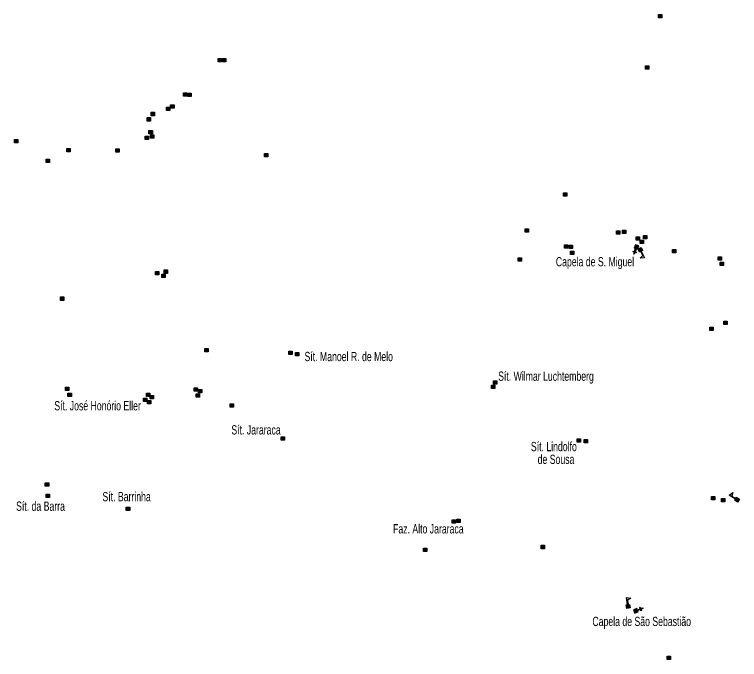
# Model space of a CAD drawing. Extents: x 647.8 to 672.9, y 6929.3 to 6957.3.
# Drawn here: x 654.09 to 660.33, y 6943.48 to 6949.04 of the extents above; entities that cross this region are included whole.
import ezdxf
from ezdxf.enums import TextEntityAlignment as Align

# ---------------------------------------------------------------- set-up
doc = ezdxf.new("R2010")
doc.units = 0
doc.header["$LTSCALE"] = 0.032
for name, color, linetype, lineweight in [('2', 7, 'Continuous', 25), ('4', 7, 'Continuous', 25), ('6', 7, 'Continuous', 25)]:
    doc.layers.add(name, color=color, linetype=linetype, lineweight=lineweight)
doc.layers.add('61', color=7, linetype='Continuous')

msp = doc.modelspace()

# ---------------------------------------------------------------- hatches: boundary and pattern name
at = {"layer": '2'}
for points in [[(659.6357, 6949.0383), (659.6647, 6949.0383), (659.6647, 6949.0093), (659.6357, 6949.0093)], [(655.8425, 6948.6588), (655.8715, 6948.6588), (655.8715, 6948.6298), (655.8425, 6948.6298)], [(655.882, 6948.6588), (655.911, 6948.6588), (655.911, 6948.6298), (655.882, 6948.6298)], [(659.5238, 6948.5951), (659.5528, 6948.5951), (659.5528, 6948.5661), (659.5238, 6948.5661)], [(655.5442, 6948.3626), (655.5732, 6948.3626), (655.5732, 6948.3336), (655.5442, 6948.3336)], [(655.5815, 6948.3604), (655.6105, 6948.3604), (655.6105, 6948.3314), (655.5815, 6948.3314)], [(655.3994, 6948.2397), (655.4284, 6948.2397), (655.4284, 6948.2107), (655.3994, 6948.2107)], [(655.4345, 6948.2617), (655.4635, 6948.2617), (655.4635, 6948.2327), (655.4345, 6948.2327)], [(655.2326, 6948.1498), (655.2616, 6948.1498), (655.2616, 6948.1208), (655.2326, 6948.1208)], [(655.2677, 6948.1959), (655.2967, 6948.1959), (655.2967, 6948.1669), (655.2677, 6948.1669)], [(655.248, 6948.0401), (655.277, 6948.0401), (655.277, 6948.0111), (655.248, 6948.0111)], [(654.0896, 6947.9611), (654.1186, 6947.9611), (654.1186, 6947.9321), (654.0896, 6947.9321)], [(655.2151, 6947.9896), (655.2441, 6947.9896), (655.2441, 6947.9606), (655.2151, 6947.9606)], [(655.2612, 6948.0028), (655.2902, 6948.0028), (655.2902, 6947.9738), (655.2612, 6947.9738)], [(654.5394, 6947.8843), (654.5684, 6947.8843), (654.5684, 6947.8553), (654.5394, 6947.8553)], [(654.9628, 6947.8821), (654.9918, 6947.8821), (654.9918, 6947.8531), (654.9628, 6947.8531)], [(656.244, 6947.8405), (656.273, 6947.8405), (656.273, 6947.8115), (656.244, 6947.8115)], [(654.3617, 6947.7922), (654.3907, 6947.7922), (654.3907, 6947.7632), (654.3617, 6947.7632)], [(658.8174, 6947.5026), (658.8464, 6947.5026), (658.8464, 6947.4736), (658.8174, 6947.4736)], [(658.4883, 6947.1933), (658.5173, 6947.1933), (658.5173, 6947.1643), (658.4883, 6947.1643)], [(659.2737, 6947.1757), (659.3027, 6947.1757), (659.3027, 6947.1467), (659.2737, 6947.1467)], [(659.3264, 6947.1801), (659.3554, 6947.1801), (659.3554, 6947.1511), (659.3264, 6947.1511)], [(659.4438, 6947.1236), (659.4728, 6947.1236), (659.4728, 6947.0946), (659.4438, 6947.0946)], [(659.4777, 6947.0945), (659.5067, 6947.0945), (659.5067, 6947.0655), (659.4777, 6947.0655)], [(659.5084, 6947.134), (659.5374, 6947.134), (659.5374, 6947.105), (659.5084, 6947.105)], [(658.8262, 6947.0551), (658.8552, 6947.0551), (658.8552, 6947.0261), (658.8262, 6947.0261)], [(658.8678, 6947.0529), (658.8968, 6947.0529), (658.8968, 6947.0239), (658.8678, 6947.0239)], [(658.8788, 6947.0002), (658.9078, 6947.0002), (658.9078, 6946.9712), (658.8788, 6946.9712)], [(659.7585, 6947.0134), (659.7875, 6947.0134), (659.7875, 6946.9844), (659.7585, 6946.9844)], [(660.1512, 6946.9519), (660.1802, 6946.9519), (660.1802, 6946.9229), (660.1512, 6946.9229)], [(658.4291, 6946.9432), (658.4581, 6946.9432), (658.4581, 6946.9142), (658.4291, 6946.9142)], [(660.1688, 6946.9059), (660.1978, 6946.9059), (660.1978, 6946.8769), (660.1688, 6946.8769)], [(655.3796, 6946.8379), (655.4086, 6946.8379), (655.4086, 6946.8089), (655.3796, 6946.8089)], [(655.305, 6946.8247), (655.334, 6946.8247), (655.334, 6946.7957), (655.305, 6946.7957)], [(655.3577, 6946.8028), (655.3867, 6946.8028), (655.3867, 6946.7738), (655.3577, 6946.7738)], [(654.4867, 6946.6053), (654.5157, 6946.6053), (654.5157, 6946.5763), (654.4867, 6946.5763)], [(660.1995, 6946.3969), (660.2285, 6946.3969), (660.2285, 6946.3679), (660.1995, 6946.3679)], [(660.0788, 6946.3464), (660.1078, 6946.3464), (660.1078, 6946.3174), (660.0788, 6946.3174)], [(655.7284, 6946.1622), (655.7574, 6946.1622), (655.7574, 6946.1332), (655.7284, 6946.1332)], [(656.4524, 6946.138), (656.4814, 6946.138), (656.4814, 6946.109), (656.4524, 6946.109)], [(656.5095, 6946.1271), (656.5385, 6946.1271), (656.5385, 6946.0981), (656.5095, 6946.0981)], [(654.5284, 6945.8287), (654.5574, 6945.8287), (654.5574, 6945.7997), (654.5284, 6945.7997)], [(658.1987, 6945.8462), (658.2277, 6945.8462), (658.2277, 6945.8172), (658.1987, 6945.8172)], [(658.2163, 6945.8835), (658.2453, 6945.8835), (658.2453, 6945.8545), (658.2163, 6945.8545)], [(654.5503, 6945.776), (654.5793, 6945.776), (654.5793, 6945.747), (654.5503, 6945.747)], [(655.2261, 6945.776), (655.2551, 6945.776), (655.2551, 6945.747), (655.2261, 6945.747)], [(655.6363, 6945.8221), (655.6653, 6945.8221), (655.6653, 6945.7931), (655.6363, 6945.7931)], [(655.6539, 6945.7717), (655.6829, 6945.7717), (655.6829, 6945.7427), (655.6539, 6945.7427)], [(655.6736, 6945.809), (655.7026, 6945.809), (655.7026, 6945.78), (655.6736, 6945.78)], [(655.1997, 6945.7344), (655.2287, 6945.7344), (655.2287, 6945.7054), (655.1997, 6945.7054)], [(655.2348, 6945.7146), (655.2638, 6945.7146), (655.2638, 6945.6856), (655.2348, 6945.6856)], [(655.2568, 6945.7563), (655.2858, 6945.7563), (655.2858, 6945.7273), (655.2568, 6945.7273)], [(655.9478, 6945.6839), (655.9768, 6945.6839), (655.9768, 6945.6549), (655.9478, 6945.6549)], [(656.3866, 6945.4009), (656.4156, 6945.4009), (656.4156, 6945.3719), (656.3866, 6945.3719)], [(658.9358, 6945.3833), (658.9648, 6945.3833), (658.9648, 6945.3543), (658.9358, 6945.3543)], [(658.9951, 6945.379), (659.0241, 6945.379), (659.0241, 6945.35), (658.9951, 6945.35)], [(654.3551, 6945.0038), (654.3841, 6945.0038), (654.3841, 6944.9748), (654.3551, 6944.9748)], [(654.3617, 6944.9073), (654.3907, 6944.9073), (654.3907, 6944.8783), (654.3617, 6944.8783)], [(660.0942, 6944.8875), (660.1232, 6944.8875), (660.1232, 6944.8585), (660.0942, 6944.8585)], [(660.1798, 6944.87), (660.2088, 6944.87), (660.2088, 6944.841), (660.1798, 6944.841)], [(655.0527, 6944.7954), (655.0817, 6944.7954), (655.0817, 6944.7664), (655.0527, 6944.7664)], [(657.8587, 6944.6857), (657.8877, 6944.6857), (657.8877, 6944.6567), (657.8587, 6944.6567)], [(657.9004, 6944.6923), (657.9294, 6944.6923), (657.9294, 6944.6633), (657.9004, 6944.6633)], [(658.6265, 6944.4663), (658.6555, 6944.4663), (658.6555, 6944.4373), (658.6265, 6944.4373)], [(657.613, 6944.4422), (657.642, 6944.4422), (657.642, 6944.4132), (657.613, 6944.4132)], [(659.7103, 6943.512), (659.7393, 6943.512), (659.7393, 6943.483), (659.7103, 6943.483)]]:
    msp.add_hatch(color=256, dxfattribs=at).paths.add_polyline_path(points)
at = {"layer": '4'}
for points in [[(659.4873, 6947.0324), (659.5002, 6947.0054), (659.4731, 6946.9924), (659.4602, 6947.0195)], [(660.3187, 6944.8385), (660.2932, 6944.8543), (660.309, 6944.8798), (660.3345, 6944.864)], [(659.3634, 6943.9234), (659.3585, 6943.953), (659.3881, 6943.9579), (659.393, 6943.9283)]]:
    msp.add_hatch(color=256, dxfattribs=at).paths.add_polyline_path(points)
at = {"layer": '6'}
for points in [[(659.4397, 6947.0218), (659.4444, 6947.0202), (659.4355, 6946.9941), (659.4474, 6946.9901), (659.4457, 6946.9854), (659.4339, 6946.9894), (659.4282, 6946.9729), (659.4235, 6946.9744), (659.4292, 6946.9911), (659.4174, 6946.9951), (659.4189, 6946.9998), (659.4308, 6946.9958)], [(659.4562, 6947.0161), (659.466, 6947.0445), (659.4375, 6947.0542), (659.4278, 6947.0258)], [(659.4495, 6943.9209), (659.4215, 6943.9101), (659.4323, 6943.8821), (659.4603, 6943.8929)], [(659.4558, 6943.9045), (659.454, 6943.9092), (659.4796, 6943.9191), (659.4752, 6943.9307), (659.4798, 6943.9325), (659.4843, 6943.9209), (659.5006, 6943.9272), (659.5024, 6943.9225), (659.4861, 6943.9162), (659.4906, 6943.9045), (659.4859, 6943.9027), (659.4814, 6943.9144)]]:
    msp.add_hatch(color=256, dxfattribs=at).paths.add_polyline_path(points)

# ---------------------------------------------------------------- linework, layer by layer
at = {"layer": '2'}
for points in [[(659.6357, 6949.0383), (659.6647, 6949.0383), (659.6647, 6949.0093), (659.6357, 6949.0093)], [(655.8425, 6948.6588), (655.8715, 6948.6588), (655.8715, 6948.6298), (655.8425, 6948.6298)], [(655.882, 6948.6588), (655.911, 6948.6588), (655.911, 6948.6298), (655.882, 6948.6298)], [(659.5238, 6948.5951), (659.5528, 6948.5951), (659.5528, 6948.5661), (659.5238, 6948.5661)], [(655.5442, 6948.3626), (655.5732, 6948.3626), (655.5732, 6948.3336), (655.5442, 6948.3336)], [(655.5815, 6948.3604), (655.6105, 6948.3604), (655.6105, 6948.3314), (655.5815, 6948.3314)], [(655.3994, 6948.2397), (655.4284, 6948.2397), (655.4284, 6948.2107), (655.3994, 6948.2107)], [(655.4345, 6948.2617), (655.4635, 6948.2617), (655.4635, 6948.2327), (655.4345, 6948.2327)], [(655.2326, 6948.1498), (655.2616, 6948.1498), (655.2616, 6948.1208), (655.2326, 6948.1208)], [(655.2677, 6948.1959), (655.2967, 6948.1959), (655.2967, 6948.1669), (655.2677, 6948.1669)], [(655.248, 6948.0401), (655.277, 6948.0401), (655.277, 6948.0111), (655.248, 6948.0111)], [(654.0896, 6947.9611), (654.1186, 6947.9611), (654.1186, 6947.9321), (654.0896, 6947.9321)], [(655.2151, 6947.9896), (655.2441, 6947.9896), (655.2441, 6947.9606), (655.2151, 6947.9606)], [(655.2612, 6948.0028), (655.2902, 6948.0028), (655.2902, 6947.9738), (655.2612, 6947.9738)], [(654.5394, 6947.8843), (654.5684, 6947.8843), (654.5684, 6947.8553), (654.5394, 6947.8553)], [(654.9628, 6947.8821), (654.9918, 6947.8821), (654.9918, 6947.8531), (654.9628, 6947.8531)], [(656.244, 6947.8405), (656.273, 6947.8405), (656.273, 6947.8115), (656.244, 6947.8115)], [(654.3617, 6947.7922), (654.3907, 6947.7922), (654.3907, 6947.7632), (654.3617, 6947.7632)], [(658.8174, 6947.5026), (658.8464, 6947.5026), (658.8464, 6947.4736), (658.8174, 6947.4736)], [(658.4883, 6947.1933), (658.5173, 6947.1933), (658.5173, 6947.1643), (658.4883, 6947.1643)], [(659.2737, 6947.1757), (659.3027, 6947.1757), (659.3027, 6947.1467), (659.2737, 6947.1467)], [(659.3264, 6947.1801), (659.3554, 6947.1801), (659.3554, 6947.1511), (659.3264, 6947.1511)], [(659.4438, 6947.1236), (659.4728, 6947.1236), (659.4728, 6947.0946), (659.4438, 6947.0946)], [(659.4777, 6947.0945), (659.5067, 6947.0945), (659.5067, 6947.0655), (659.4777, 6947.0655)], [(659.5084, 6947.134), (659.5374, 6947.134), (659.5374, 6947.105), (659.5084, 6947.105)], [(658.8262, 6947.0551), (658.8552, 6947.0551), (658.8552, 6947.0261), (658.8262, 6947.0261)], [(658.8678, 6947.0529), (658.8968, 6947.0529), (658.8968, 6947.0239), (658.8678, 6947.0239)], [(658.8788, 6947.0002), (658.9078, 6947.0002), (658.9078, 6946.9712), (658.8788, 6946.9712)], [(659.7585, 6947.0134), (659.7875, 6947.0134), (659.7875, 6946.9844), (659.7585, 6946.9844)], [(660.1512, 6946.9519), (660.1802, 6946.9519), (660.1802, 6946.9229), (660.1512, 6946.9229)], [(658.4291, 6946.9432), (658.4581, 6946.9432), (658.4581, 6946.9142), (658.4291, 6946.9142)], [(660.1688, 6946.9059), (660.1978, 6946.9059), (660.1978, 6946.8769), (660.1688, 6946.8769)], [(655.3796, 6946.8379), (655.4086, 6946.8379), (655.4086, 6946.8089), (655.3796, 6946.8089)], [(655.305, 6946.8247), (655.334, 6946.8247), (655.334, 6946.7957), (655.305, 6946.7957)], [(655.3577, 6946.8028), (655.3867, 6946.8028), (655.3867, 6946.7738), (655.3577, 6946.7738)], [(654.4867, 6946.6053), (654.5157, 6946.6053), (654.5157, 6946.5763), (654.4867, 6946.5763)], [(660.1995, 6946.3969), (660.2285, 6946.3969), (660.2285, 6946.3679), (660.1995, 6946.3679)], [(660.0788, 6946.3464), (660.1078, 6946.3464), (660.1078, 6946.3174), (660.0788, 6946.3174)], [(655.7284, 6946.1622), (655.7574, 6946.1622), (655.7574, 6946.1332), (655.7284, 6946.1332)], [(656.4524, 6946.138), (656.4814, 6946.138), (656.4814, 6946.109), (656.4524, 6946.109)], [(656.5095, 6946.1271), (656.5385, 6946.1271), (656.5385, 6946.0981), (656.5095, 6946.0981)], [(654.5284, 6945.8287), (654.5574, 6945.8287), (654.5574, 6945.7997), (654.5284, 6945.7997)], [(658.1987, 6945.8462), (658.2277, 6945.8462), (658.2277, 6945.8172), (658.1987, 6945.8172)], [(658.2163, 6945.8835), (658.2453, 6945.8835), (658.2453, 6945.8545), (658.2163, 6945.8545)], [(654.5503, 6945.776), (654.5793, 6945.776), (654.5793, 6945.747), (654.5503, 6945.747)], [(655.2261, 6945.776), (655.2551, 6945.776), (655.2551, 6945.747), (655.2261, 6945.747)], [(655.6363, 6945.8221), (655.6653, 6945.8221), (655.6653, 6945.7931), (655.6363, 6945.7931)], [(655.6539, 6945.7717), (655.6829, 6945.7717), (655.6829, 6945.7427), (655.6539, 6945.7427)], [(655.6736, 6945.809), (655.7026, 6945.809), (655.7026, 6945.78), (655.6736, 6945.78)], [(655.1997, 6945.7344), (655.2287, 6945.7344), (655.2287, 6945.7054), (655.1997, 6945.7054)], [(655.2348, 6945.7146), (655.2638, 6945.7146), (655.2638, 6945.6856), (655.2348, 6945.6856)], [(655.2568, 6945.7563), (655.2858, 6945.7563), (655.2858, 6945.7273), (655.2568, 6945.7273)], [(655.9478, 6945.6839), (655.9768, 6945.6839), (655.9768, 6945.6549), (655.9478, 6945.6549)], [(656.3866, 6945.4009), (656.4156, 6945.4009), (656.4156, 6945.3719), (656.3866, 6945.3719)], [(658.9358, 6945.3833), (658.9648, 6945.3833), (658.9648, 6945.3543), (658.9358, 6945.3543)], [(658.9951, 6945.379), (659.0241, 6945.379), (659.0241, 6945.35), (658.9951, 6945.35)], [(654.3551, 6945.0038), (654.3841, 6945.0038), (654.3841, 6944.9748), (654.3551, 6944.9748)], [(654.3617, 6944.9073), (654.3907, 6944.9073), (654.3907, 6944.8783), (654.3617, 6944.8783)], [(660.0942, 6944.8875), (660.1232, 6944.8875), (660.1232, 6944.8585), (660.0942, 6944.8585)], [(660.1798, 6944.87), (660.2088, 6944.87), (660.2088, 6944.841), (660.1798, 6944.841)], [(655.0527, 6944.7954), (655.0817, 6944.7954), (655.0817, 6944.7664), (655.0527, 6944.7664)], [(657.8587, 6944.6857), (657.8877, 6944.6857), (657.8877, 6944.6567), (657.8587, 6944.6567)], [(657.9004, 6944.6923), (657.9294, 6944.6923), (657.9294, 6944.6633), (657.9004, 6944.6633)], [(658.6265, 6944.4663), (658.6555, 6944.4663), (658.6555, 6944.4373), (658.6265, 6944.4373)], [(657.613, 6944.4422), (657.642, 6944.4422), (657.642, 6944.4132), (657.613, 6944.4132)], [(659.7103, 6943.512), (659.7393, 6943.512), (659.7393, 6943.483), (659.7103, 6943.483)]]:
    msp.add_lwpolyline(points, close=True, dxfattribs=at)
at = {"layer": '4'}
for p, q in [((659.4889, 6947), (659.4844, 6946.9978)), ((660.2997, 6944.8649), (660.3024, 6944.8692)), ((659.3708, 6943.955), (659.3758, 6943.9558))]:
    msp.add_line(p, q, dxfattribs=at)
for points in [[(659.4873, 6947.0324), (659.5002, 6947.0054), (659.4731, 6946.9924), (659.4602, 6947.0195)], [(659.4889, 6947), (659.5158, 6946.9436), (659.4789, 6946.9398), (659.5014, 6946.9622), (659.4844, 6946.9978)], [(660.2997, 6944.8649), (660.2466, 6944.8978), (660.2757, 6944.921), (660.2688, 6944.89), (660.3024, 6944.8692)], [(660.3187, 6944.8385), (660.2932, 6944.8543), (660.309, 6944.8798), (660.3345, 6944.864)], [(659.3708, 6943.955), (659.3606, 6944.0167), (659.3972, 6944.0101), (659.3693, 6943.9948), (659.3758, 6943.9558)], [(659.3634, 6943.9234), (659.3585, 6943.953), (659.3881, 6943.9579), (659.393, 6943.9283)]]:
    msp.add_lwpolyline(points, close=True, dxfattribs=at)
at = {"layer": '6'}
for points in [[(659.4397, 6947.0218), (659.4444, 6947.0202), (659.4355, 6946.9941), (659.4474, 6946.9901), (659.4457, 6946.9854), (659.4339, 6946.9894), (659.4282, 6946.9729), (659.4235, 6946.9744), (659.4292, 6946.9911), (659.4174, 6946.9951), (659.4189, 6946.9998), (659.4308, 6946.9958)], [(659.4562, 6947.0161), (659.466, 6947.0445), (659.4375, 6947.0542), (659.4278, 6947.0258)], [(659.4495, 6943.9209), (659.4215, 6943.9101), (659.4323, 6943.8821), (659.4603, 6943.8929)], [(659.4558, 6943.9045), (659.454, 6943.9092), (659.4796, 6943.9191), (659.4752, 6943.9307), (659.4798, 6943.9325), (659.4843, 6943.9209), (659.5006, 6943.9272), (659.5024, 6943.9225), (659.4861, 6943.9162), (659.4906, 6943.9045), (659.4859, 6943.9027), (659.4814, 6943.9144)]]:
    msp.add_lwpolyline(points, close=True, dxfattribs=at)

# ---------------------------------------------------------------- texts
at = {"layer": '61', "width": 0.7}
for s, p in [('Capela de S. Miguel', (659.4269, 6946.8691)), ('Sít. José Honório Eller', (655.1777, 6945.6286)), ('Sít. Jararaca', (656.3823, 6945.421)), ('Sít. Lindolfo', (658.9332, 6945.2772)), (' de Sousa ', (658.9332, 6945.1672)), ('Sít. Barrinha', (655.2634, 6944.8459)), ('Faz. Alto Jararaca', (657.958, 6944.5687)), ('Capela de São Sebastião', (659.9169, 6943.7711))]:
    msp.add_text(s, height=0.08, dxfattribs=at).set_placement(p, align=Align.RIGHT)
for s, p in [('Sít. Manoel R. de Melo', (656.5876, 6946.0526)), ('Sít. Wilmar Luchtemberg', (658.2557, 6945.8832)), ('Sít. da Barra', (654.1035, 6944.7638))]:
    msp.add_text(s, height=0.08, dxfattribs=at).set_placement(p)

doc.saveas('drawing.dxf')
